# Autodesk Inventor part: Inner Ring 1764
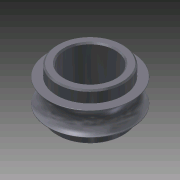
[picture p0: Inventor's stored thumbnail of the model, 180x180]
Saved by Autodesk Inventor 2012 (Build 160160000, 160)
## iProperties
Created: 2009-01
Part Number: Inner Ring 1764
Document SubType Name: Modeling
Designer: pmulligan
Density: 1 g/cm^3
Material: Default
Author: pmulligan
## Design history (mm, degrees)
sketch "Sketch1"
  geometry: L1 (-25.486, -2.288)-(-25.486, -4.462); L2 (-25.486, -9.034)-(-25.486, -11.209); L3 (-25.486, -11.209)-(-23.899, -11.209); L4 (-23.899, -11.209)-(-23.899, -2.288); L5 (-23.899, -2.288)-(-25.486, -2.288); L6 (-19.136, -1.735)-(-19.136, -11.209); L7 (-27.039, -9.034)-(-25.486, -9.034); L8 (-25.486, -4.462)-(-27.039, -4.462); A1 r 2.286 centre (-27.874, -6.748) between (-27.066, -8.887) and (-27.066, -4.61); A2 r 0.076 centre (-27.039, -4.538) between (-27.039, -4.462) and (-27.066, -4.61); A3 r 0.076 centre (-27.039, -8.958) between (-27.066, -8.887) and (-27.039, -9.034)
  constraints: 16 end point, 6 point on circle, 6 tangent, 3 centre point, 2 collinear, 2 parallel, 2 perpendicular, 1 equal radius, 1 vertical
  dimensions: "d0" = 2.17472 distance of L2.start L2.end; "d2" = 2.17472 distance of L1.start L1.end; "d3" = 1.5875 distance of L2.end L3.end; "d7" = 4.572 diameter of A1; "d8" = 0.0762 radius of A2; "d16" = 4.7625 distance between parallel lines of L6 L4; "d20" = 3.14037 distance from line of L8.end L4; "d21" = 3.9751 distance from line of A1.centre L4
revolve "Revolution1" sketch "Sketch1" stored, may be unused: angle "d9" = 90 deg
chamfer "Chamfer1" distance "d10" = 0.254; stored, may be unused: second distance "d11" = 3.175, angle "d12" = 45 deg
chamfer "Chamfer2" distance "d13" = 0.254; stored, may be unused: second distance "d14" = 3.175, angle "d15" = 45 deg
body "Solid1"
